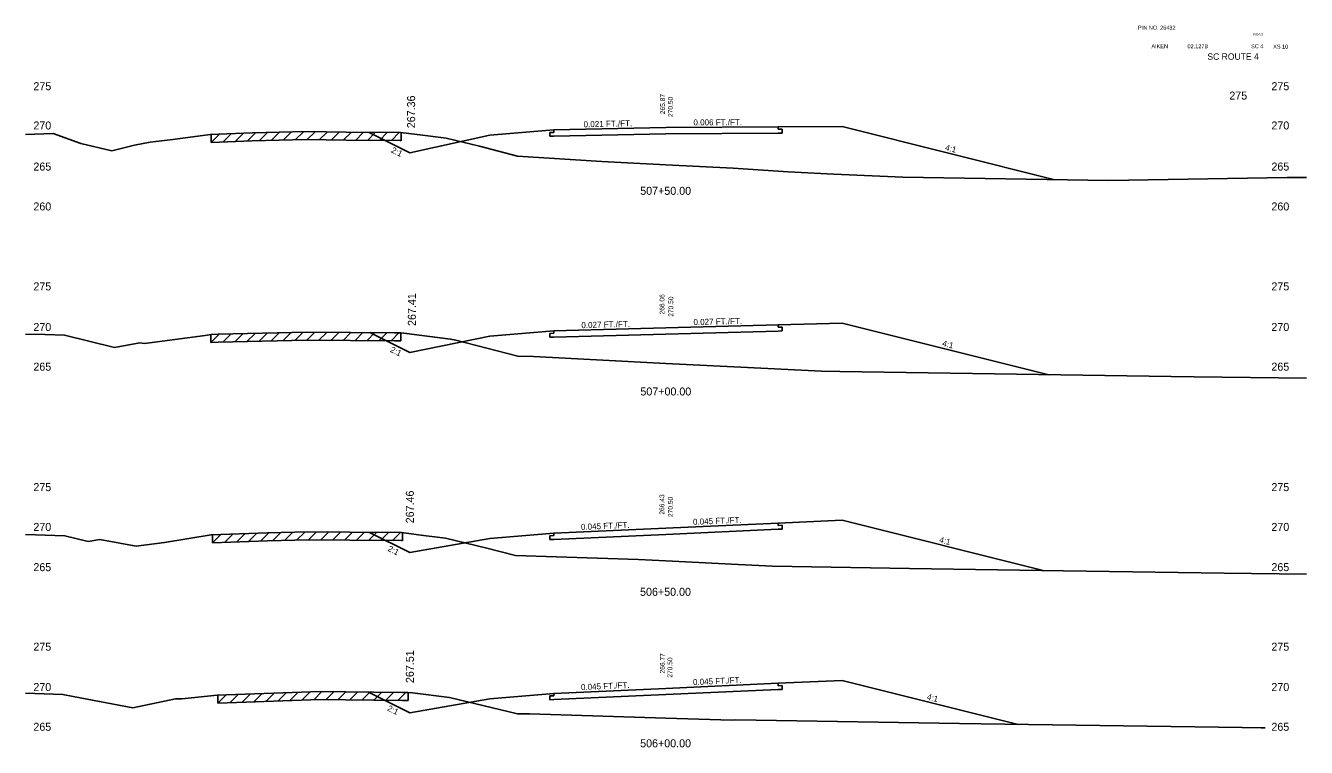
# Model space of a CAD drawing. Extents: x 883 to 1160, y 1002 to 4323.
# Drawn here: x 1000 to 1160, y 2048.1 to 2138.2 of the extents above; entities that cross this region are included whole.
import ezdxf

# ---------------------------------------------------------------- set-up
doc = ezdxf.new("R2010")
doc.units = 0
for name, color, linetype in [('Level 1', 7, 'Continuous'), ('Level 10', 7, 'Continuous'), ('Level 11', 7, 'Continuous'), ('Level 12', 7, 'Continuous'), ('Level 3', 7, 'Continuous'), ('Level 32', 7, 'Continuous'), ('Level 33', 7, 'Continuous'), ('Level 59', 7, 'Continuous'), ('Level 6', 7, 'Continuous'), ('Level 60', 7, 'Continuous'), ('Level 61', 7, 'Continuous'), ('Level 7', 7, 'Continuous')]:
    doc.layers.add(name, color=color, linetype=linetype)

msp = doc.modelspace()

# ---------------------------------------------------------------- linework, layer by layer
at = {"layer": 'Level 11'}
for p, q in [((1066, 2124.91), (1065.5, 2124.9)), ((1065.5, 2124.9), (1065.5, 2124.42)), ((1066, 2125.21), (1066, 2124.91)), ((1094, 2125.29), (1094, 2125.59)), ((1094.5, 2125.29), (1094, 2125.29)), ((1094, 2124.81), (1094.5, 2124.81)), ((1094.5, 2124.81), (1094.5, 2125.29)), ((1065.5, 2124.42), (1066, 2124.43)), ((1094, 2100.58), (1094, 2100.88)), ((1066, 2099.82), (1065.5, 2099.8)), ((1065.5, 2099.8), (1065.5, 2099.32)), ((1065.5, 2099.32), (1066, 2099.34)), ((1066, 2100.12), (1066, 2099.82)), ((1094.5, 2100.6), (1094, 2100.58)), ((1094, 2100.1), (1094.5, 2100.12)), ((1094.5, 2100.12), (1094.5, 2100.6)), ((1094, 2075.83), (1094, 2076.13)), ((1094.5, 2075.85), (1094, 2075.83)), ((1094, 2075.35), (1094.5, 2075.37)), ((1094.5, 2075.37), (1094.5, 2075.85)), ((1066, 2074.57), (1065.5, 2074.55)), ((1065.5, 2074.55), (1065.5, 2074.07)), ((1065.5, 2074.07), (1066, 2074.09)), ((1066, 2074.87), (1066, 2074.57)), ((1094, 2055.83), (1094, 2056.13)), ((1066, 2054.57), (1065.5, 2054.55)), ((1065.5, 2054.55), (1065.5, 2054.07)), ((1066, 2054.87), (1066, 2054.57)), ((1094.5, 2055.85), (1094, 2055.83)), ((1094, 2055.35), (1094.5, 2055.37)), ((1094.5, 2055.37), (1094.5, 2055.85)), ((1065.5, 2054.07), (1066, 2054.09))]:
    msp.add_line(p, q, dxfattribs=at)
at = {"layer": 'Level 12'}
for p, q in [((1094, 2124.81), (1080, 2124.72)), ((1080, 2124.72), (1066, 2124.43)), ((1080, 2099.72), (1066, 2099.34)), ((1094, 2100.1), (1080, 2099.72)), ((1094, 2075.35), (1080, 2074.72)), ((1080, 2074.72), (1066, 2074.09)), ((1080, 2054.72), (1066, 2054.09)), ((1094, 2055.35), (1080, 2054.72))]:
    msp.add_line(p, q, dxfattribs=at)
at = {"layer": 'Level 59'}
for p, q in [((1066, 2125.21), (1080, 2125.5)), ((1080, 2125.5), (1094, 2125.59)), ((1080, 2100.5), (1094, 2100.88)), ((1066, 2100.12), (1080, 2100.5)), ((1066, 2074.87), (1080, 2075.5)), ((1080, 2075.5), (1094, 2076.13)), ((1080, 2055.5), (1094, 2056.13)), ((1066, 2054.87), (1080, 2055.5))]:
    msp.add_line(p, q, dxfattribs=at)
at = {"layer": 'Level 6'}
for p, q in [((1058, 2124.54), (1066, 2125.21)), ((1094, 2125.59), (1102, 2125.64)), ((1094, 2100.88), (1102, 2101.1)), ((1058, 2099.45), (1066, 2100.12)), ((1094, 2076.13), (1102, 2076.49)), ((1058, 2074.2), (1066, 2074.87)), ((1094, 2056.13), (1102, 2056.49)), ((1058, 2054.2), (1066, 2054.87))]:
    msp.add_line(p, q, dxfattribs=at)
at = {"layer": 'Level 60'}
for p, q in [((1023.07, 2124.65), (1028.29, 2124.84)), ((1028.29, 2124.84), (1035.06, 2125)), ((1035.06, 2125), (1040.06, 2124.92)), ((1040.06, 2124.92), (1046.83, 2124.88)), ((1046.83, 2124.88), (1048.93, 2124.64)), ((1000, 2124.63), (1003.46, 2124.77)), ((1003.46, 2124.77), (1006.89, 2123.53)), ((1006.89, 2123.53), (1010.75, 2122.61)), ((1010.75, 2122.61), (1013.62, 2123.33)), ((1013.62, 2123.33), (1015.56, 2123.69)), ((1015.56, 2123.69), (1018.39, 2124.03)), ((1018.39, 2124.03), (1023.07, 2124.65)), ((1048.93, 2124.64), (1052.52, 2124.18)), ((1052.52, 2124.18), (1056.7, 2123.17)), ((1056.7, 2123.17), (1061.46, 2121.95)), ((1061.46, 2121.95), (1071.98, 2121.28)), ((1071.98, 2121.28), (1080, 2120.87)), ((1080, 2120.87), (1088.39, 2120.44)), ((1088.39, 2120.44), (1095.27, 2119.97)), ((1095.27, 2119.97), (1100.97, 2119.68)), ((1100.97, 2119.68), (1109.58, 2119.3)), ((1109.58, 2119.3), (1135.28, 2118.9)), ((1135.28, 2118.9), (1157.59, 2119.28)), ((1157.59, 2119.28), (1160, 2119.26)), ((1000, 2099.71), (1002.39, 2099.67)), ((1002.39, 2099.67), (1004.86, 2099.57)), ((1004.86, 2099.57), (1011.1, 2098.07)), ((1014.84, 2098.55), (1022.44, 2099.56)), ((1022.44, 2099.56), (1023.18, 2099.68)), ((1023.18, 2099.68), (1024.07, 2099.71)), ((1024.07, 2099.71), (1035.07, 2099.96)), ((1035.07, 2099.96), (1046.08, 2099.89)), ((1046.08, 2099.89), (1046.89, 2099.89)), ((1046.89, 2099.89), (1047.23, 2099.84)), ((1047.23, 2099.84), (1053.09, 2099.11)), ((1011.1, 2098.07), (1014.26, 2098.65)), ((1014.26, 2098.65), (1014.84, 2098.55)), ((1053.09, 2099.11), (1053.75, 2098.95)), ((1053.75, 2098.95), (1061.49, 2096.97)), ((1061.49, 2096.97), (1063.46, 2096.91)), ((1063.46, 2096.91), (1080, 2096.06)), ((1080, 2096.06), (1090.19, 2095.55)), ((1090.19, 2095.55), (1099.41, 2095.09)), ((1099.41, 2095.09), (1101.72, 2095.05)), ((1101.72, 2095.05), (1143.11, 2094.41)), ((1143.11, 2094.41), (1145.98, 2094.37)), ((1145.98, 2094.37), (1160, 2094.21)), ((1000, 2074.71), (1004.91, 2074.52)), ((1004.91, 2074.52), (1007.8, 2073.83)), ((1007.8, 2073.83), (1009.26, 2074.1)), ((1009.26, 2074.1), (1013.81, 2073.24)), ((1013.81, 2073.24), (1017.35, 2073.72)), ((1017.35, 2073.72), (1023.18, 2074.65)), ((1023.18, 2074.65), (1030.21, 2074.91)), ((1030.21, 2074.91), (1035.36, 2075.02)), ((1035.36, 2075.02), (1040.51, 2074.99)), ((1040.51, 2074.99), (1046.95, 2074.94)), ((1046.95, 2074.94), (1049.71, 2074.58)), ((1049.71, 2074.58), (1052.44, 2074.24)), ((1052.44, 2074.24), (1057.61, 2073.01)), ((1057.61, 2073.01), (1061.21, 2072.09)), ((1061.21, 2072.09), (1076.57, 2071.6)), ((1076.57, 2071.6), (1080, 2071.43)), ((1080, 2071.43), (1089.03, 2070.97)), ((1089.03, 2070.97), (1093.3, 2070.76)), ((1093.3, 2070.76), (1110.43, 2070.47)), ((1110.43, 2070.47), (1129.64, 2070.18)), ((1129.64, 2070.18), (1149.74, 2069.89)), ((1149.74, 2069.89), (1160, 2069.77)), ((1000, 2054.9), (1004.65, 2054.71)), ((1004.65, 2054.71), (1005.92, 2054.49)), ((1005.92, 2054.49), (1013.38, 2053.08)), ((1019.52, 2054.18), (1023.93, 2054.63)), ((1023.93, 2054.63), (1035.63, 2055.06)), ((1035.63, 2055.06), (1036.4, 2055.09)), ((1036.4, 2055.09), (1047.09, 2055)), ((1047.09, 2055), (1047.74, 2055)), ((1047.74, 2055), (1048.34, 2054.93)), ((1048.34, 2054.93), (1052.94, 2054.34)), ((1013.38, 2053.08), (1018.74, 2054.17)), ((1018.74, 2054.17), (1019.52, 2054.18)), ((1052.94, 2054.34), (1061.44, 2052.32)), ((1061.44, 2052.32), (1062.95, 2052.3)), ((1062.95, 2052.3), (1080, 2051.77)), ((1080, 2051.77), (1088.24, 2051.51)), ((1088.24, 2051.51), (1088.72, 2051.56)), ((1088.72, 2051.56), (1116.68, 2051.1)), ((1116.68, 2051.1), (1119.36, 2051.06)), ((1119.36, 2051.06), (1151.96, 2050.6)), ((1151.96, 2050.6), (1154.37, 2050.57)), ((1154.37, 2050.57), (1154.85, 2050.57))]:
    msp.add_line(p, q, dxfattribs=at)
at = {"layer": 'Level 61'}
for p, q in [((1027.23, 2124.8), (1026.19, 2123.77)), ((1028.72, 2124.85), (1027.69, 2123.82)), ((1030.21, 2124.89), (1029.19, 2123.86)), ((1031.71, 2124.92), (1030.69, 2123.9)), ((1033.21, 2124.96), (1032.19, 2123.93)), ((1034.71, 2124.99), (1033.69, 2123.97)), ((1036.17, 2124.98), (1035.19, 2124)), ((1037.67, 2124.95), (1036.69, 2123.97)), ((1039.17, 2124.93), (1038.19, 2123.95)), ((1040.68, 2124.91), (1039.69, 2123.92)), ((1042.18, 2124.9), (1041.19, 2123.91)), ((1043.68, 2124.89), (1042.69, 2123.9)), ((1045.18, 2124.89), (1044.19, 2123.89)), ((1046.68, 2124.88), (1045.69, 2123.88)), ((1046.91, 2123.87), (1046.91, 2124.87)), ((1024.23, 2124.69), (1023.19, 2123.65)), ((1023.19, 2124.65), (1023.19, 2123.65)), ((1023.19, 2123.65), (1028.29, 2123.84)), ((1025.73, 2124.75), (1024.69, 2123.71)), ((1028.29, 2123.84), (1035.06, 2124)), ((1035.06, 2124), (1040.06, 2123.92)), ((1040.06, 2123.92), (1046.83, 2123.88)), ((1046.83, 2123.88), (1046.91, 2123.87)), ((1024.19, 2099.71), (1023.15, 2098.67)), ((1023.15, 2099.67), (1023.15, 2098.67)), ((1025.67, 2099.75), (1024.65, 2098.72)), ((1027.17, 2099.78), (1026.15, 2098.76)), ((1028.67, 2099.81), (1027.65, 2098.79)), ((1030.17, 2099.85), (1029.15, 2098.82)), ((1031.67, 2099.88), (1030.65, 2098.86)), ((1033.17, 2099.92), (1032.15, 2098.89)), ((1034.67, 2099.95), (1033.65, 2098.93)), ((1036.14, 2099.95), (1035.15, 2098.96)), ((1037.64, 2099.94), (1036.65, 2098.95)), ((1039.14, 2099.94), (1038.15, 2098.94)), ((1040.64, 2099.93), (1039.65, 2098.93)), ((1042.14, 2099.92), (1041.15, 2098.92)), ((1043.64, 2099.91), (1042.65, 2098.91)), ((1045.14, 2099.9), (1044.15, 2098.91)), ((1046.64, 2099.89), (1045.65, 2098.9)), ((1046.89, 2098.89), (1046.89, 2099.89)), ((1023.15, 2098.67), (1023.18, 2098.68)), ((1023.18, 2098.68), (1024.07, 2098.71)), ((1024.07, 2098.71), (1035.07, 2098.96)), ((1035.07, 2098.96), (1046.08, 2098.89)), ((1046.08, 2098.89), (1046.89, 2098.89)), ((1046.89, 2098.89), (1046.89, 2098.89)), ((1024.38, 2074.69), (1023.34, 2073.65)), ((1023.34, 2074.65), (1023.34, 2073.65)), ((1023.34, 2073.65), (1030.21, 2073.91)), ((1025.88, 2074.75), (1024.84, 2073.71)), ((1027.38, 2074.8), (1026.34, 2073.76)), ((1028.88, 2074.86), (1027.84, 2073.82)), ((1030.38, 2074.91), (1029.34, 2073.87)), ((1030.21, 2073.91), (1035.36, 2074.02)), ((1031.87, 2074.94), (1030.84, 2073.92)), ((1033.37, 2074.98), (1032.34, 2073.95)), ((1034.87, 2075.01), (1033.84, 2073.99)), ((1036.34, 2075.02), (1035.34, 2074.02)), ((1035.36, 2074.02), (1040.51, 2073.99)), ((1037.84, 2075.01), (1036.84, 2074.01)), ((1039.34, 2075), (1038.34, 2074.01)), ((1040.84, 2074.99), (1039.84, 2074)), ((1040.51, 2073.99), (1046.95, 2073.94)), ((1042.33, 2074.98), (1041.34, 2073.99)), ((1043.83, 2074.96), (1042.84, 2073.97)), ((1045.33, 2074.95), (1044.34, 2073.96)), ((1046.83, 2074.94), (1045.84, 2073.95)), ((1046.95, 2073.94), (1047.09, 2073.92)), ((1047.09, 2073.92), (1047.09, 2074.92)), ((1025.04, 2054.67), (1024.01, 2053.63)), ((1024.01, 2054.63), (1024.01, 2053.63)), ((1026.54, 2054.73), (1025.51, 2053.69)), ((1028.04, 2054.78), (1027.01, 2053.75)), ((1029.55, 2054.84), (1028.51, 2053.8)), ((1031.05, 2054.89), (1030.01, 2053.86)), ((1032.55, 2054.95), (1031.51, 2053.91)), ((1034.05, 2055.01), (1033.01, 2053.97)), ((1035.55, 2055.06), (1034.51, 2054.02)), ((1037.02, 2055.09), (1036.01, 2054.08)), ((1038.5, 2055.07), (1037.51, 2054.08)), ((1040, 2055.06), (1039.01, 2054.07)), ((1041.5, 2055.05), (1040.51, 2054.06)), ((1043, 2055.03), (1042.01, 2054.04)), ((1044.5, 2055.02), (1043.51, 2054.03)), ((1046, 2055.01), (1045.01, 2054.02)), ((1047.5, 2055), (1046.51, 2054)), ((1047.81, 2053.99), (1047.81, 2054.99)), ((1024.01, 2053.63), (1035.63, 2054.06)), ((1035.63, 2054.06), (1036.4, 2054.09)), ((1036.4, 2054.09), (1047.09, 2054)), ((1047.09, 2054), (1047.74, 2054)), ((1047.74, 2054), (1047.81, 2053.99))]:
    msp.add_line(p, q, dxfattribs=at)
at = {"layer": 'Level 7'}
for p, q in [((1042.91, 2124.9), (1048, 2122.36)), ((1102, 2125.64), (1128.56, 2119)), ((1048, 2122.36), (1058, 2124.54)), ((1102, 2101.1), (1127.83, 2094.64)), ((1043, 2099.91), (1048, 2097.41)), ((1048, 2097.41), (1058, 2099.45)), ((1102, 2076.49), (1127.1, 2070.22)), ((1042.97, 2074.97), (1048, 2072.46)), ((1048, 2072.46), (1058, 2074.2)), ((1102, 2056.49), (1123.99, 2050.99)), ((1042.84, 2055.04), (1048, 2052.46)), ((1048, 2052.46), (1058, 2054.2))]:
    msp.add_line(p, q, dxfattribs=at)

# ---------------------------------------------------------------- texts
at = {"layer": 'Level 1'}
for s, height, p in [('PIN NO. 26432', 0.5, (1138.97, 2137.73)), ('AIKEN', 0.5, (1140.64, 2135.41)), ('02.127B', 0.5, (1145.15, 2135.41)), ('SC ROUTE 4', 0.8, (1147.63, 2133.97)), ('SC 4', 0.5, (1153.09, 2135.41)), ('XS 10', 0.5, (1155.85, 2135.37)), ('507+50.00', 1, (1076.78, 2117.11)), ('507+00.00', 1, (1076.8, 2092.06)), ('506+50.00', 1, (1076.76, 2067.05)), ('506+00.00', 1, (1076.77, 2048.14))]:
    msp.add_text(s, height=height, dxfattribs=at).set_placement(p)
at = {"layer": 'Level 10'}
for s, p in [('265.87', (1079.87, 2127.17)), ('266.06', (1079.81, 2102.17)), ('266.43', (1079.79, 2077.18)), ('266.77', (1079.85, 2057.35))]:
    msp.add_text(s, height=0.6, rotation=90, dxfattribs=at).set_placement(p)
at = {"layer": 'Level 3'}
for s, height, p in [('ROAD', 0.3, (1153.38, 2137)), (' 275', 1, (1000.6, 2130.17)), (' 275', 1, (1150, 2129)), (' 275', 1, (1155.26, 2130.17)), (' 270', 1, (1000.6, 2125.27)), (' 270', 1, (1155.26, 2125.27)), (' 265', 1, (1000.6, 2120.14)), (' 265', 1, (1155.26, 2120.14)), (' 260', 1, (1000.6, 2115.16)), (' 260', 1, (1155.26, 2115.16)), (' 275', 1, (1000.6, 2105.18)), (' 275', 1, (1155.26, 2105.18)), (' 270', 1, (1000.6, 2100.11)), (' 270', 1, (1155.26, 2100.11)), (' 265', 1, (1000.6, 2095.16)), (' 265', 1, (1155.26, 2095.16)), (' 275', 1, (1000.6, 2080.12)), (' 275', 1, (1155.26, 2080.12)), (' 270', 1, (1000.6, 2075.15)), (' 270', 1, (1155.26, 2075.15)), (' 265', 1, (1000.6, 2070.13)), (' 265', 1, (1155.26, 2070.13)), (' 275', 1, (1000.6, 2060.2)), (' 275', 1, (1155.26, 2060.2)), (' 270', 1, (1000.6, 2055.16)), (' 270', 1, (1155.26, 2055.16)), (' 265', 1, (1000.6, 2050.2)), (' 265', 1, (1155.26, 2050.2))]:
    msp.add_text(s, height=height, dxfattribs=at).set_placement(p)
at = {"layer": 'Level 32'}
for s, rotation, p in [('0.021 FT./FT.', 1.1916, (1069.71, 2125.54)), ('0.006 FT./FT.', 0.3723, (1083.43, 2125.77)), ('4:1', 345.9638, (1114.82, 2122.69)), ('2:1', 333.435, (1045.59, 2122.45)), ('0.027 FT./FT.', 1.5631, (1069.44, 2100.46)), ('0.027 FT./FT.', 1.565, (1083.44, 2100.84)), ('2:1', 333.435, (1045.48, 2097.54)), ('4:1', 345.9638, (1114.46, 2098.24)), ('0.045 FT./FT.', 2.5766, (1083.39, 2075.9)), ('0.045 FT./FT.', 2.5766, (1069.39, 2075.27)), ('4:1', 345.9638, (1114.09, 2073.72)), ('2:1', 333.435, (1045.17, 2072.7)), ('0.045 FT./FT.', 2.5766, (1069.39, 2055.27)), ('0.045 FT./FT.', 2.5766, (1083.39, 2055.9)), ('4:1', 345.9638, (1112.54, 2054.11)), ('2:1', 333.435, (1045.11, 2052.77))]:
    msp.add_text(s, height=0.75, rotation=rotation, dxfattribs=at).set_placement(p)
at = {"layer": 'Level 33'}
for s, p in [('267.36', (1048.66, 2125.42)), ('267.41', (1048.75, 2100.74)), ('267.46', (1048.5, 2076.1)), ('267.51', (1048.5, 2056.16))]:
    msp.add_text(s, height=1, rotation=90, dxfattribs=at).set_placement(p)
at = {"layer": 'Level 59'}
for p in [(1080.85, 2126.59), (1080.91, 2101.65), (1080.85, 2076.65), (1080.79, 2056.59)]:
    msp.add_text(' 270.50', height=0.6, rotation=90, dxfattribs=at).set_placement(p)

doc.saveas('drawing.dxf')
